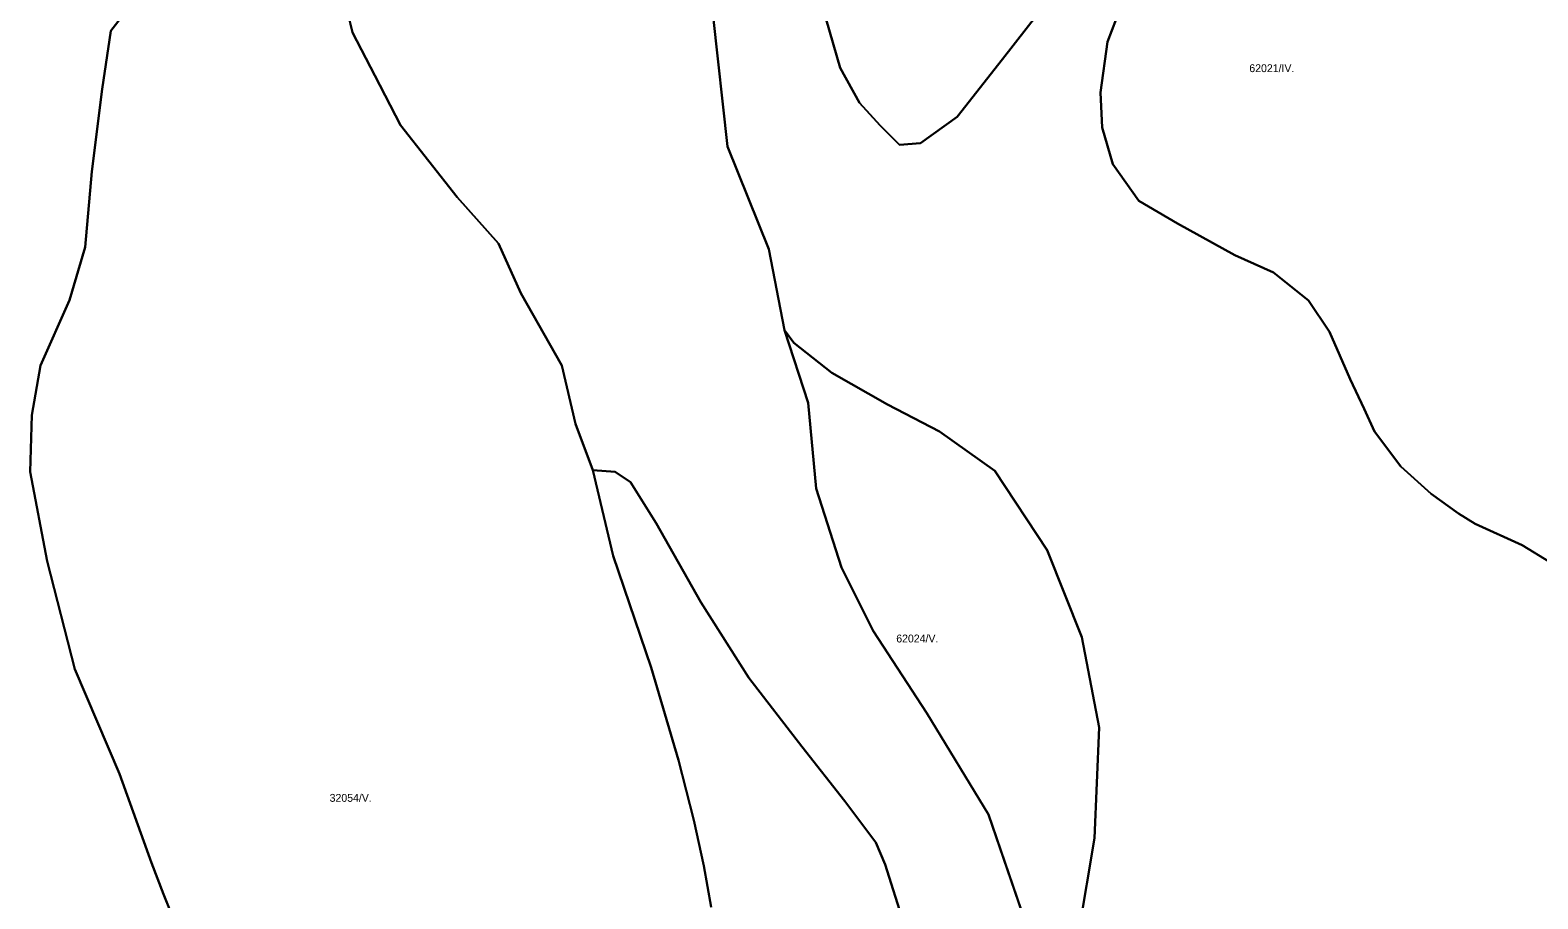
# Model space of a CAD drawing. Extents: x -521621 to -516761, y -1190184 to -1184927.
# Drawn here: x -519994 to -519227, y -1188534 to -1188092 of the extents above; entities that cross this region are included whole.
import ezdxf

# ---------------------------------------------------------------- set-up
doc = ezdxf.new("R2010")
doc.units = 0
doc.layers.add('BPEJ_s', color=7, linetype='Continuous')

msp = doc.modelspace()

# ---------------------------------------------------------------- linework, layer by layer
at = {"layer": 'BPEJ_s'}
for p, q in [((-519829.89, -1188093.37), (-519836.87, -1188064.56)), ((-519937.21, -1188072.42), (-519952.92, -1188092.5)), ((-519646.37, -1188085.32), (-519639.13, -1188151.35)), ((-519952.92, -1188092.5), (-519957.28, -1188122.18)), ((-519818.54, -1188115.2), (-519829.89, -1188093.37)), ((-519805.46, -1188140.52), (-519818.54, -1188115.2)), ((-519957.28, -1188122.18), (-519962.51, -1188164.09)), ((-519776.66, -1188177.19), (-519805.46, -1188140.52)), ((-519639.13, -1188151.35), (-519618.2, -1188203.69)), ((-519962.51, -1188164.09), (-519966, -1188202.51)), ((-519755.72, -1188200.76), (-519776.66, -1188177.19)), ((-519966, -1188202.51), (-519973.86, -1188229.57)), ((-519744.38, -1188226.08), (-519755.72, -1188200.76)), ((-519618.2, -1188203.69), (-519610.15, -1188244.76)), ((-519973.86, -1188229.57), (-519988.69, -1188262.75)), ((-519723.44, -1188262.75), (-519744.38, -1188226.08)), ((-519610.15, -1188244.76), (-519598.08, -1188281.81)), ((-519988.69, -1188262.75), (-519993.05, -1188288.07)), ((-519716.46, -1188292.43), (-519723.44, -1188262.75)), ((-519598.08, -1188281.81), (-519594.06, -1188325.29)), ((-519993.05, -1188288.07), (-519993.93, -1188316.88)), ((-519707.73, -1188316.01), (-519716.46, -1188292.43)), ((-519993.93, -1188316.88), (-519985.2, -1188362.28)), ((-519696.39, -1188316.88), (-519707.73, -1188316.01)), ((-519688.53, -1188322.12), (-519696.39, -1188316.88)), ((-519675.45, -1188343.07), (-519688.53, -1188322.12)), ((-519594.06, -1188325.29), (-519581.18, -1188365.56)), ((-519652.76, -1188383.24), (-519675.45, -1188343.07)), ((-519985.2, -1188362.28), (-519971.24, -1188417.29)), ((-519581.18, -1188365.56), (-519565.09, -1188397.77)), ((-519628.33, -1188421.65), (-519652.76, -1188383.24)), ((-519565.09, -1188397.77), (-519537.72, -1188439.64)), ((-519971.24, -1188417.29), (-519948.55, -1188470.54)), ((-519601.28, -1188456.57), (-519628.33, -1188421.65)), ((-519537.72, -1188439.64), (-519506.34, -1188491.18)), ((-519579.47, -1188484.51), (-519601.28, -1188456.57)), ((-519948.55, -1188470.54), (-519932.23, -1188515.82)), ((-519563.76, -1188505.47), (-519579.47, -1188484.51)), ((-519506.34, -1188491.18), (-519485.41, -1188552.38)), ((-519558.88, -1188516.72), (-519563.76, -1188505.47)), ((-519932.23, -1188515.82), (-519926.01, -1188531.81)), ((-519549.61, -1188546.12), (-519558.88, -1188516.72)), ((-519926.01, -1188531.81), (-519893.15, -1188613.14))]:
    msp.add_line(p, q, dxfattribs=at)
for points in [[(-519836.87, -1188064.56), (-519829.89, -1188093.37), (-519818.54, -1188115.2), (-519805.46, -1188140.52), (-519776.66, -1188177.19), (-519755.72, -1188200.76), (-519744.38, -1188226.08), (-519723.44, -1188262.75), (-519716.46, -1188292.43), (-519707.73, -1188316.01), (-519697.26, -1188359.66), (-519678.06, -1188416.41), (-519664.1, -1188463.56), (-519656.25, -1188494.12), (-519651.13, -1188517.24), (-519647.53, -1188538.38)], [(-519893.15, -1188613.14), (-519926.01, -1188531.81), (-519932.23, -1188515.82), (-519948.55, -1188470.54), (-519971.24, -1188417.29), (-519985.2, -1188362.28), (-519993.93, -1188316.88), (-519993.05, -1188288.07), (-519988.69, -1188262.75), (-519973.86, -1188229.57), (-519966, -1188202.51), (-519962.51, -1188164.09), (-519957.28, -1188122.18), (-519952.92, -1188092.5), (-519937.21, -1188072.42)], [(-519475.2, -1188075.85), (-519499.2, -1188106.98), (-519522.31, -1188136.33), (-519540.98, -1188149.67), (-519551.65, -1188150.56), (-519561.42, -1188140.78), (-519572.09, -1188129.22), (-519581.87, -1188111.43), (-519590.76, -1188080.3)], [(-519590.76, -1188080.3), (-519581.87, -1188111.43), (-519572.09, -1188129.22), (-519561.42, -1188140.78), (-519551.65, -1188150.56), (-519540.98, -1188149.67), (-519522.31, -1188136.33), (-519499.2, -1188106.98), (-519475.2, -1188075.85)], [(-519220.53, -1188362.97), (-519234.9, -1188354.21), (-519258.87, -1188343.37), (-519267.21, -1188338.16), (-519281.17, -1188328.15), (-519296.59, -1188314.18), (-519309.93, -1188296.45), (-519315.2, -1188284.86), (-519322.31, -1188269.75), (-519332.98, -1188245.73), (-519343.65, -1188229.72), (-519361.42, -1188215.49), (-519380.98, -1188206.59), (-519410.31, -1188190.59), (-519429.87, -1188179.02), (-519443.2, -1188160.34), (-519448.53, -1188141.67), (-519449.42, -1188123.88), (-519445.87, -1188098.08), (-519436.98, -1188074.96)], [(-519436.98, -1188074.96), (-519445.87, -1188098.08), (-519449.42, -1188123.88), (-519448.53, -1188141.67), (-519443.2, -1188160.34), (-519429.87, -1188179.02), (-519410.31, -1188190.59), (-519380.98, -1188206.59), (-519361.42, -1188215.49), (-519343.65, -1188229.72), (-519332.98, -1188245.73), (-519322.31, -1188269.75), (-519315.2, -1188284.86), (-519309.93, -1188296.45), (-519296.59, -1188314.18), (-519281.17, -1188328.15), (-519267.21, -1188338.16), (-519258.87, -1188343.37), (-519234.9, -1188354.21), (-519220.53, -1188362.97)], [(-519216.99, -1188971.26), (-519244.62, -1188934.05), (-519284.32, -1188884.77), (-519309.17, -1188843.09), (-519358.26, -1188755.31), (-519378.38, -1188701.36), (-519417.81, -1188644.18), (-519437.93, -1188611.17), (-519452.42, -1188585.4), (-519460.46, -1188550.77), (-519452.42, -1188503.26), (-519450, -1188446.89), (-519458.85, -1188400.99), (-519476.56, -1188356.7), (-519503.12, -1188316.44), (-519531.29, -1188296.3), (-519557.84, -1188282.61), (-519586.01, -1188266.51), (-519605.33, -1188251.21), (-519610.15, -1188244.76), (-519618.2, -1188203.69), (-519639.13, -1188151.35), (-519646.37, -1188085.32)], [(-519485.41, -1188552.38), (-519506.34, -1188491.18), (-519537.72, -1188439.64), (-519565.09, -1188397.77), (-519581.18, -1188365.56), (-519594.06, -1188325.29), (-519598.08, -1188281.81), (-519610.15, -1188244.76), (-519605.33, -1188251.21), (-519586.01, -1188266.51), (-519557.84, -1188282.61), (-519531.29, -1188296.3), (-519503.12, -1188316.44), (-519476.56, -1188356.7), (-519458.85, -1188400.99), (-519450, -1188446.89), (-519452.42, -1188503.26), (-519460.46, -1188550.77)], [(-519647.53, -1188538.38), (-519651.13, -1188517.24), (-519656.25, -1188494.12), (-519664.1, -1188463.56), (-519678.06, -1188416.41), (-519697.26, -1188359.66), (-519707.73, -1188316.01), (-519696.39, -1188316.88), (-519688.53, -1188322.12), (-519675.45, -1188343.07), (-519652.76, -1188383.24), (-519628.33, -1188421.65), (-519601.28, -1188456.57), (-519579.47, -1188484.51), (-519563.76, -1188505.47), (-519558.88, -1188516.72), (-519549.61, -1188546.12)]]:
    msp.add_lwpolyline(points, dxfattribs=at)

# ---------------------------------------------------------------- texts
for s, p in [('62021/IV.', (-519373.68, -1188113.55)), ('62024/V.', (-519553.3, -1188403.67)), ('32054/V.', (-519841.56, -1188484.75))]:
    msp.add_text(s, height=4, dxfattribs=at).set_placement(p)

doc.saveas('drawing.dxf')
